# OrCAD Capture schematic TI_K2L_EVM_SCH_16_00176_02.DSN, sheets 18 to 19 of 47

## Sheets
18 PAGE31 : K2L_AMC SECTION: size C; title: AMC connector
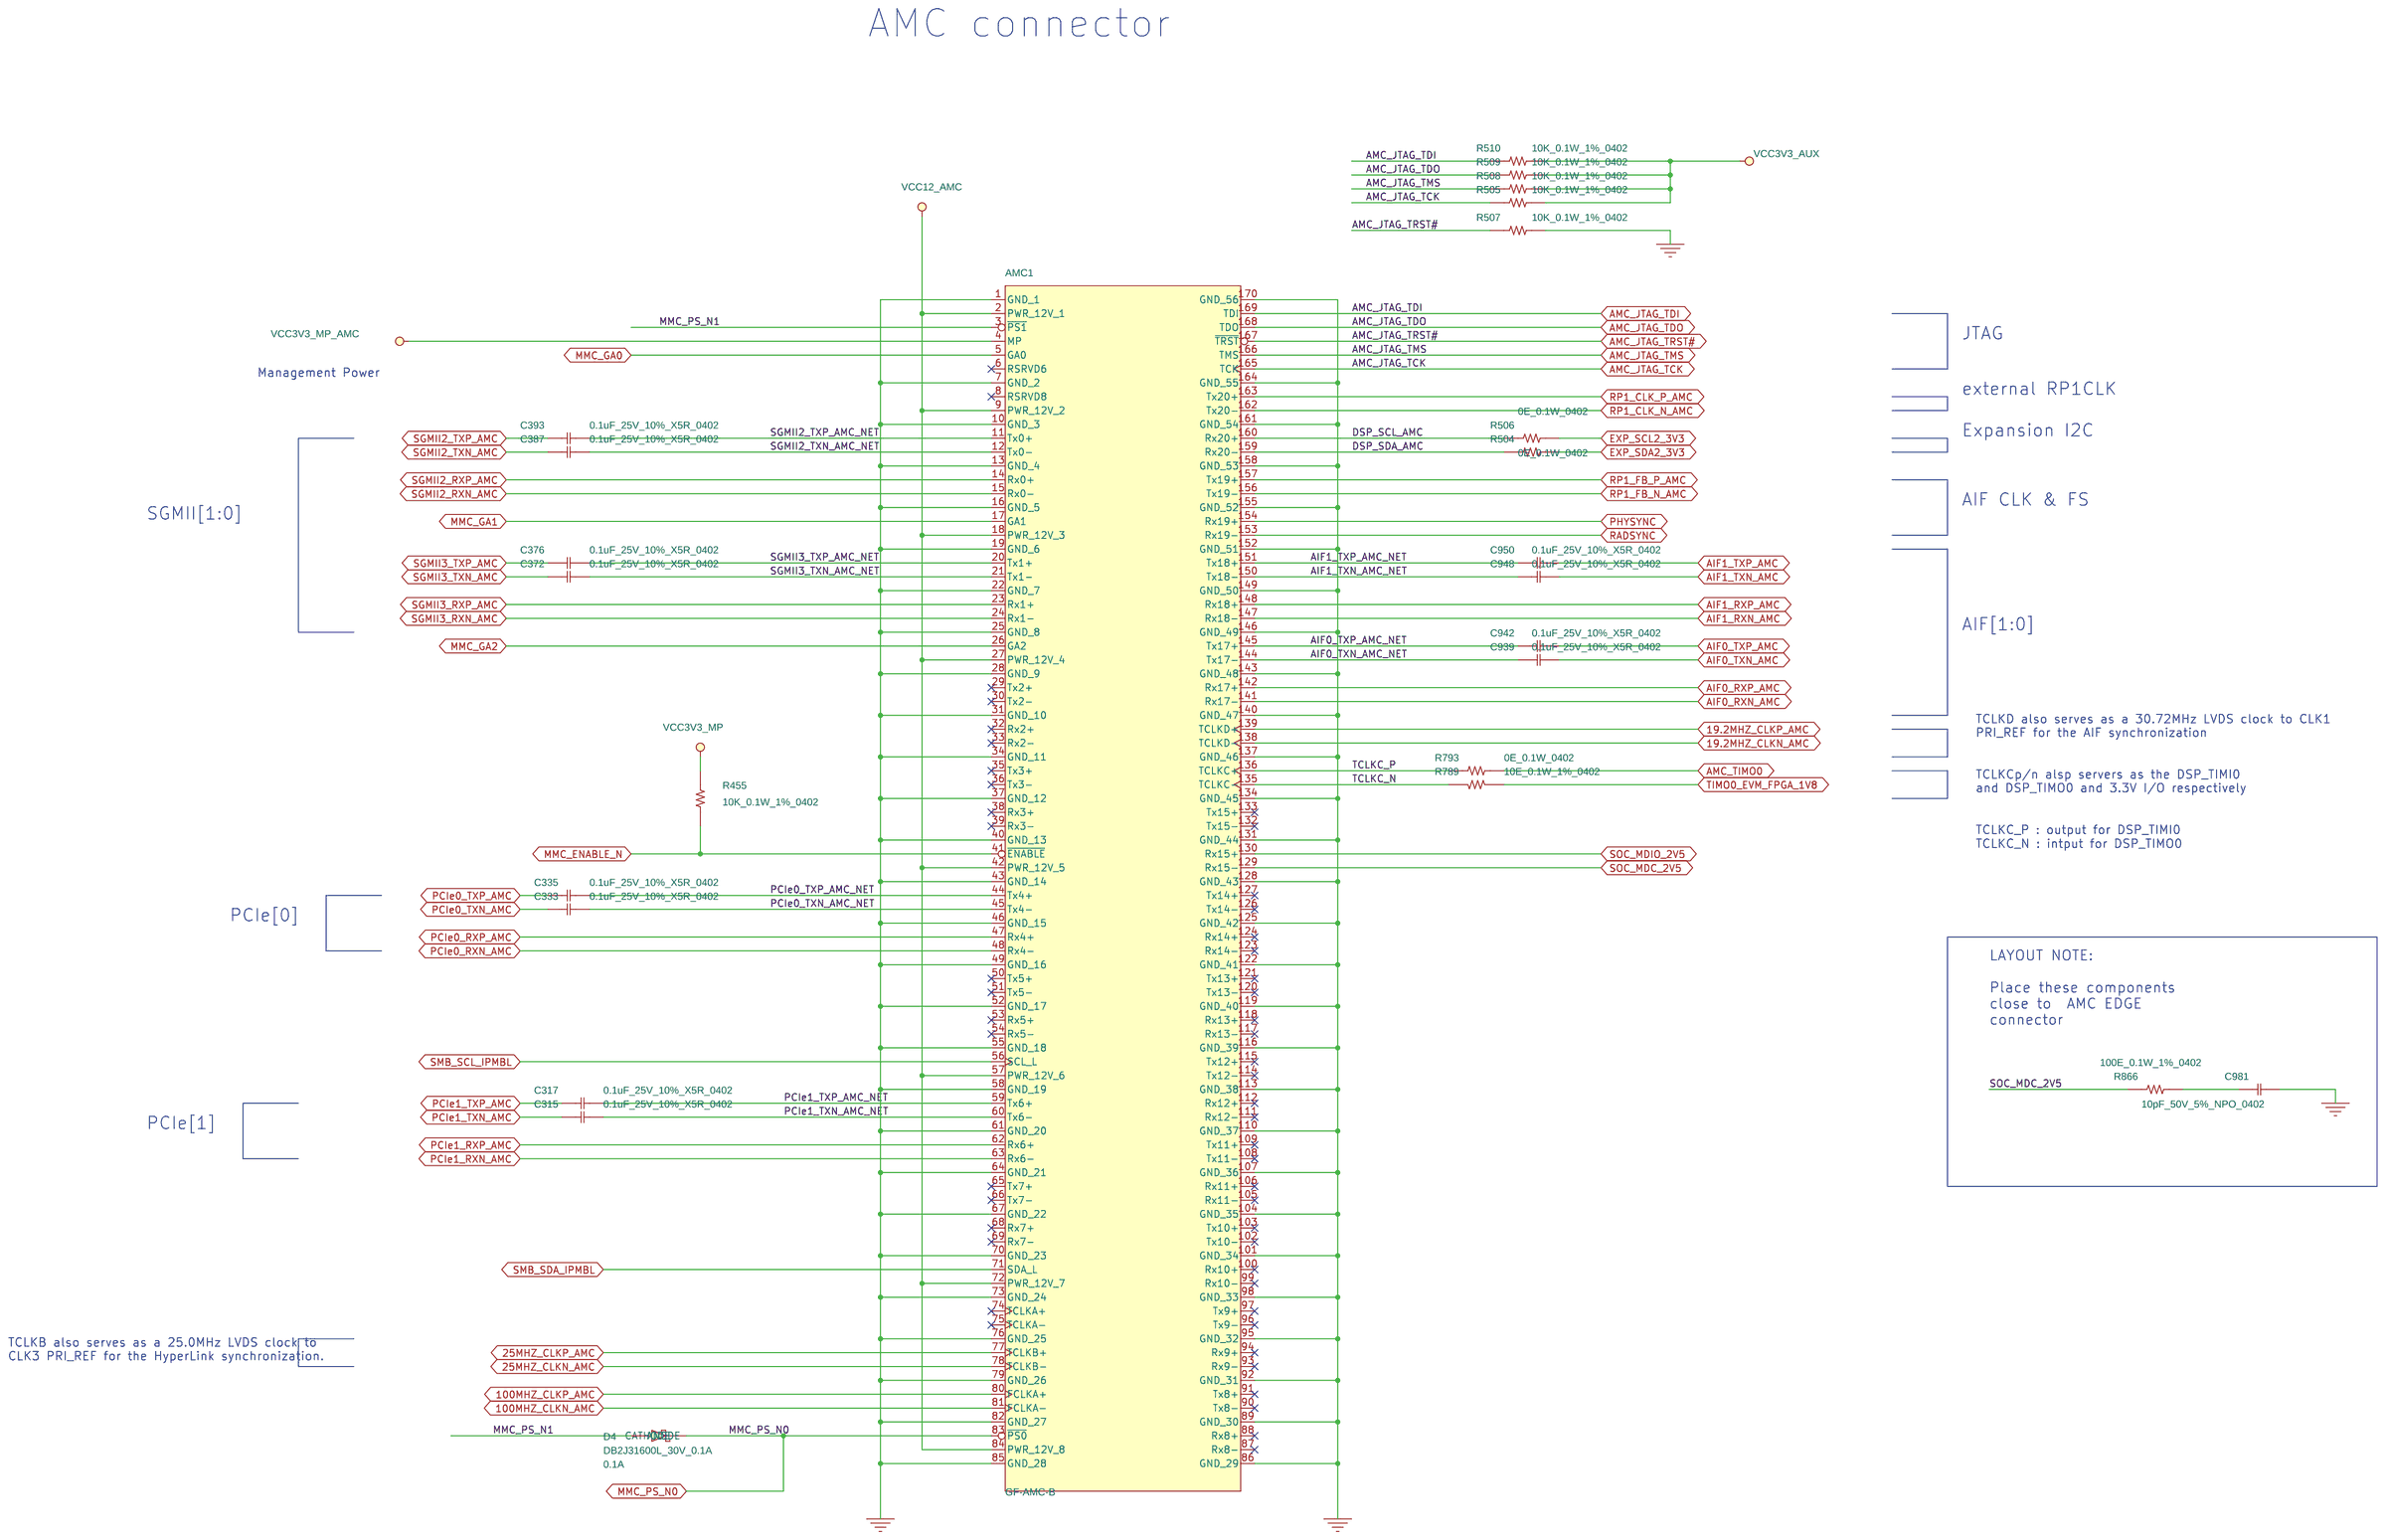
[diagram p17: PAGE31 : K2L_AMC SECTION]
19 PAGE21 : K2L_SOC-DDR3-3: size C; title: DDR3(2), 3.3vaux -> .75v DDR3 Vt, DDR3 SPD EEPROM
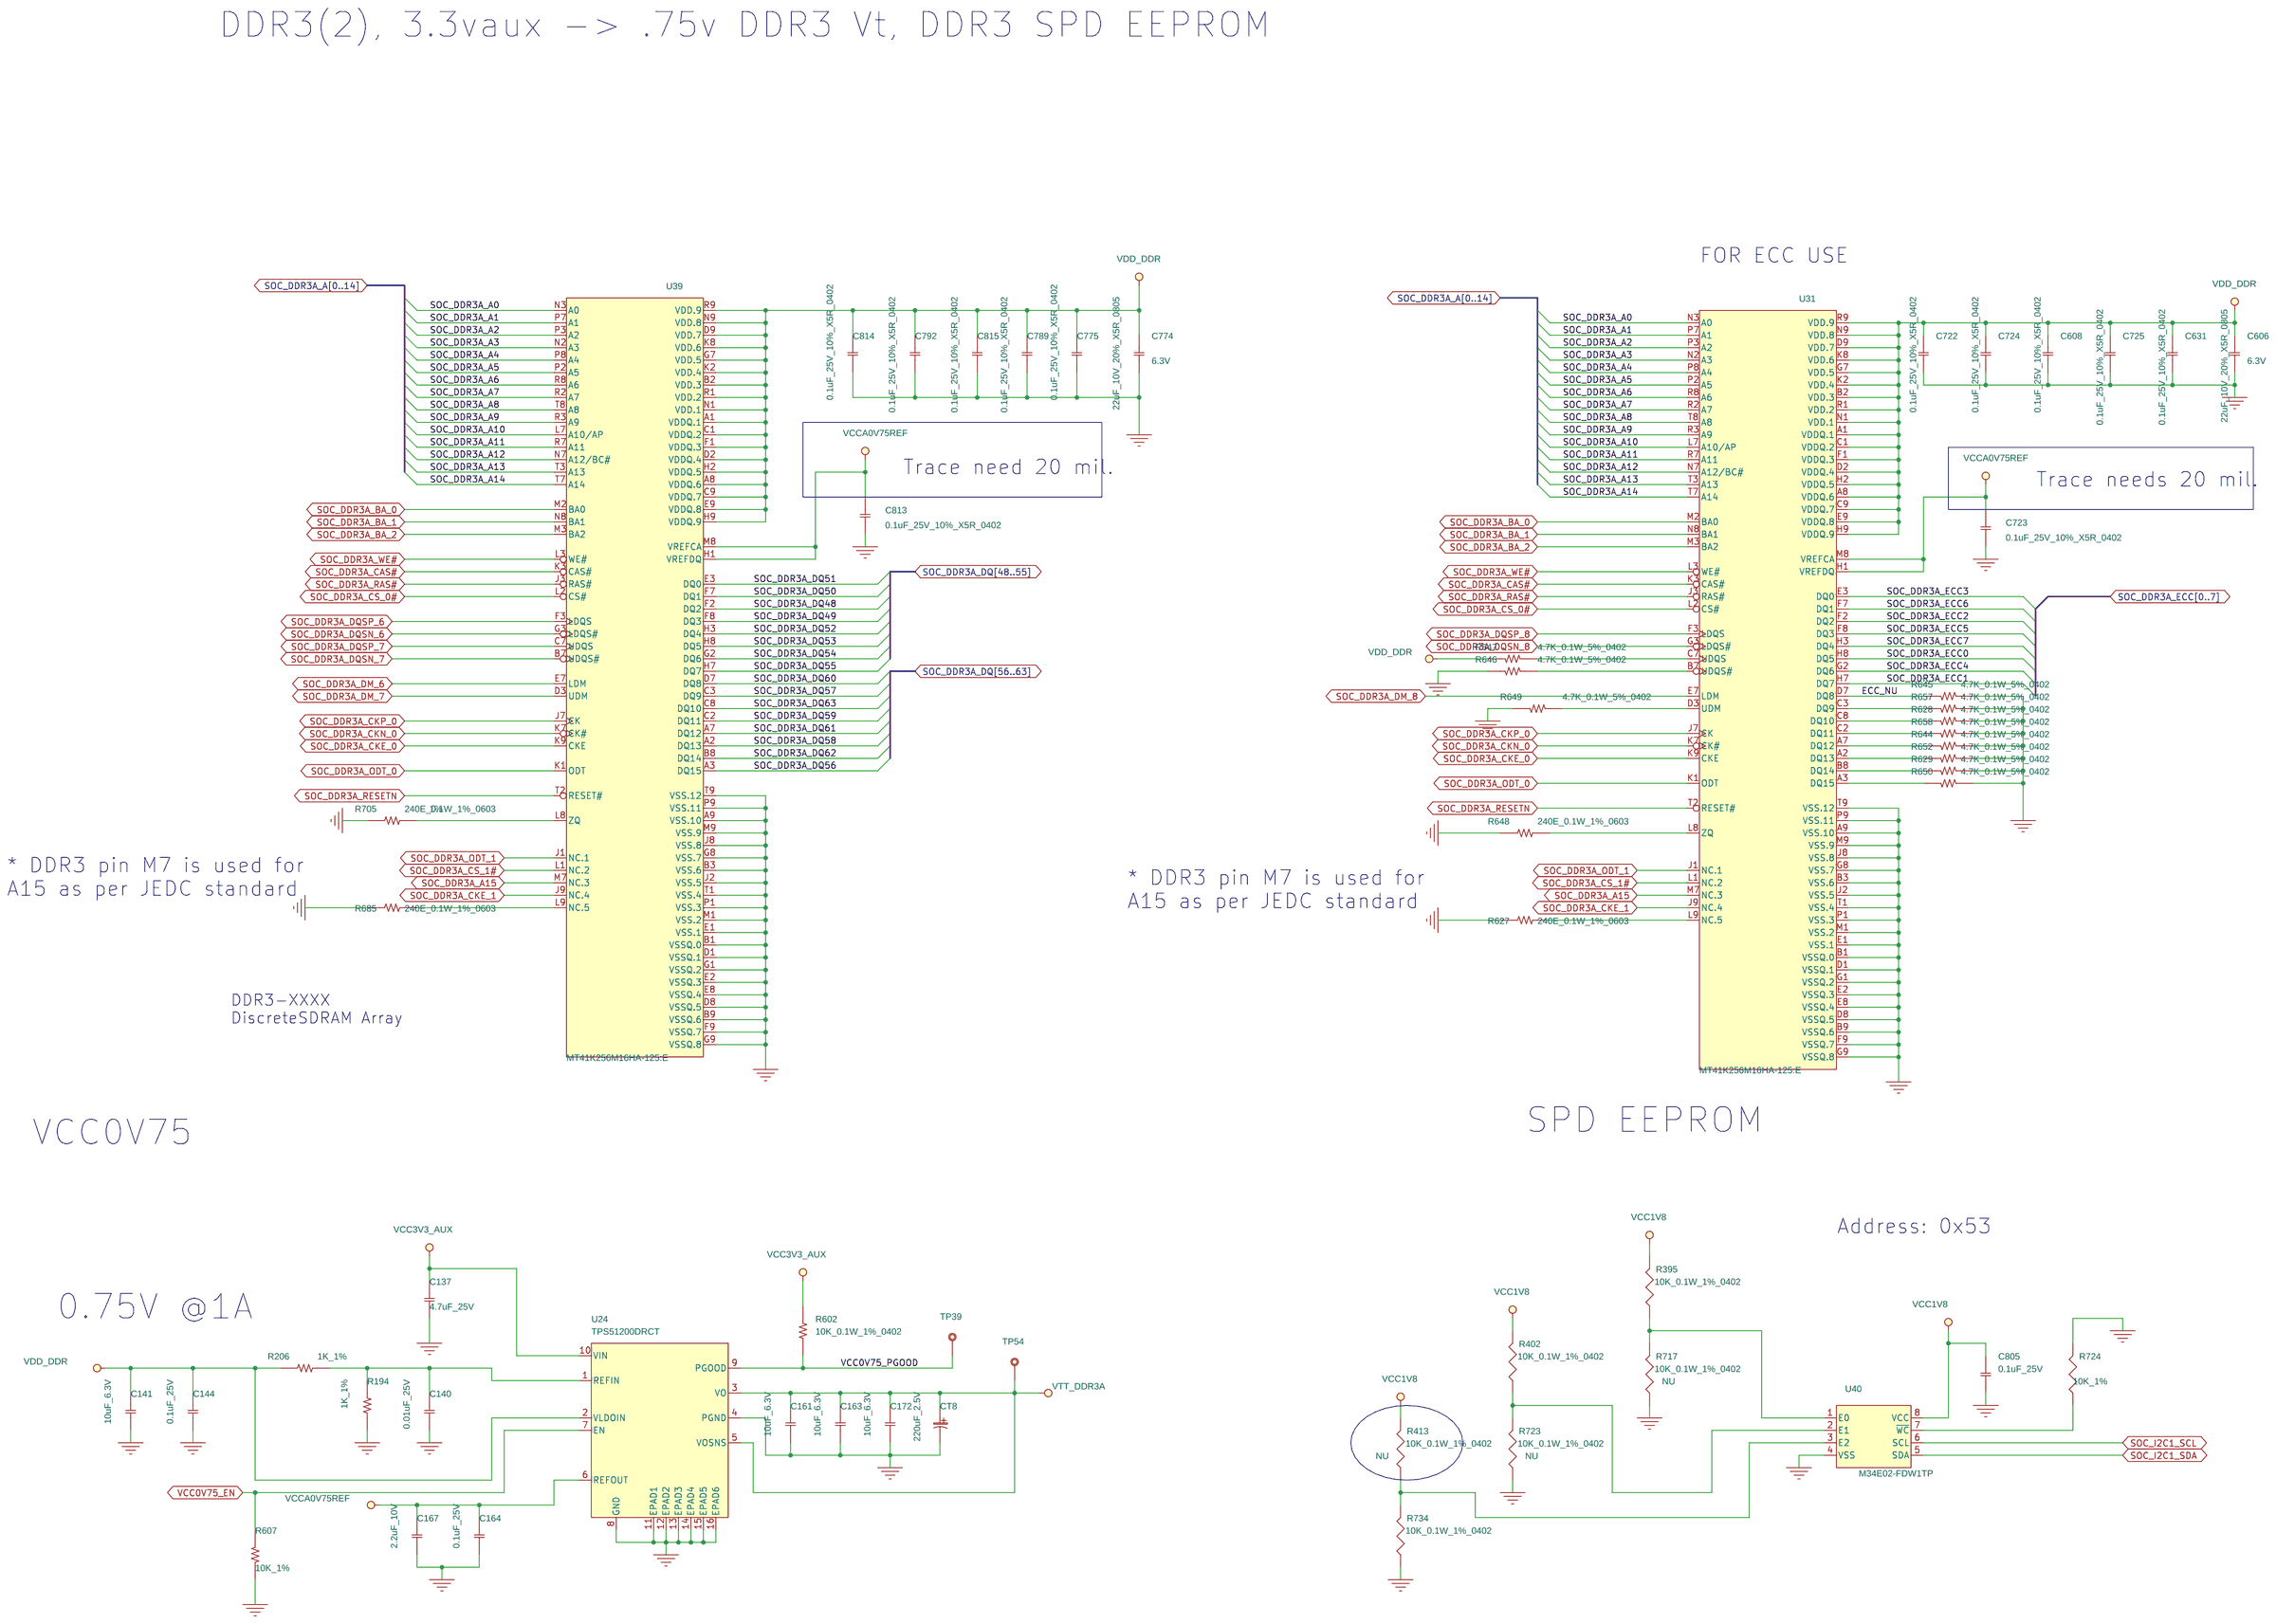
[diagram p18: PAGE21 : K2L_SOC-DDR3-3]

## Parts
sheet PAGE21 : K2L_SOC-DDR3-3
C137  4.7uF_25V  [C0603]
C140  0.01uF_25V  [C0402]
C141  10uF_6.3V  [C0603]
C144  0.1uF_25V  [C0402]
C161  10uF_6.3V  [C0603]
C163  10uF_6.3V  [C0603]
C164  0.1uF_25V  [C0402]
C167  2.2uF_10V  [C0402]
C172  10uF_6.3V  [C0603]
C606  22uF_10V_20%_X5R_0805  [C0805]
C608  0.1uF_25V_10%_X5R_0402  [C0402]
C631  0.1uF_25V_10%_X5R_0402  [C0402]
C722  0.1uF_25V_10%_X5R_0402  [C0402]
C723  0.1uF_25V_10%_X5R_0402  [C0402]
C724  0.1uF_25V_10%_X5R_0402  [C0402]
C725  0.1uF_25V_10%_X5R_0402  [C0402]
C774  22uF_10V_20%_X5R_0805  [C0805]
C775  0.1uF_25V_10%_X5R_0402  [C0402]
C789  0.1uF_25V_10%_X5R_0402  [C0402]
C792  0.1uF_25V_10%_X5R_0402  [C0402]
C805  0.1uF_25V  [C0402]
C813  0.1uF_25V_10%_X5R_0402  [C0402]
C814  0.1uF_25V_10%_X5R_0402  [C0402]
C815  0.1uF_25V_10%_X5R_0402  [C0402]
CT8  220uF_2.5V  [C_2P_114_138X118]
R194  1K_1%  [R0402]
R206  1K_1%  [R0402]
R395  10K_0.1W_1%_0402  [R0402]
R402  10K_0.1W_1%_0402  [R0402]
R413  10K_0.1W_1%_0402  [R0402]
R602  10K_0.1W_1%_0402  [R0402]
R607  10K_1%  [R0402]
R627  240E_0.1W_1%_0603  [R0603]
R628  4.7K_0.1W_5%_0402  [R0402]
R629  4.7K_0.1W_5%_0402  [R0402]
R644  4.7K_0.1W_5%_0402  [R0402]
R645  4.7K_0.1W_5%_0402  [R0402]
R646  4.7K_0.1W_5%_0402  [R0402]
R647  4.7K_0.1W_5%_0402  [R0402]
R648  240E_0.1W_1%_0603  [R0603]
R649  4.7K_0.1W_5%_0402  [R0402]
R650  4.7K_0.1W_5%_0402  [R0402]
R652  4.7K_0.1W_5%_0402  [R0402]
R657  4.7K_0.1W_5%_0402  [R0402]
R658  4.7K_0.1W_5%_0402  [R0402]
R685  240E_0.1W_1%_0603  [R0603]
R705  240E_0.1W_1%_0603  [R0603]
R717  10K_0.1W_1%_0402  [R0402]
R723  10K_0.1W_1%_0402  [R0402]
R724  10K_1%  [R0402]
R734  10K_0.1W_1%_0402  [R0402]
TP39  TP  [TP-S40]
TP54  TP  [TP-S40]
U24  TPS51200DRCT  [QFN10P_20_118x118_TP94x65V5]
U31  MT41K256M16HA-125:E  [FBGA80P_9X14_96_EINF]
U39  MT41K256M16HA-125:E  [FBGA80P_9X14_96_EINF]
U40  M34E02-FDW1TP  [TSSOP65P640_8]
sheet PAGE31 : K2L_AMC SECTION
AMC1  GF-AMC-B  [GF-AMC-B]
C315  0.1uF_25V_10%_X5R_0402  [C0402]
C317  0.1uF_25V_10%_X5R_0402  [C0402]
C333  0.1uF_25V_10%_X5R_0402  [C0402]
C335  0.1uF_25V_10%_X5R_0402  [C0402]
C372  0.1uF_25V_10%_X5R_0402  [C0402]
C376  0.1uF_25V_10%_X5R_0402  [C0402]
C387  0.1uF_25V_10%_X5R_0402  [C0402]
C393  0.1uF_25V_10%_X5R_0402  [C0402]
C939  0.1uF_25V_10%_X5R_0402  [C0402]
C942  0.1uF_25V_10%_X5R_0402  [C0402]
C948  0.1uF_25V_10%_X5R_0402  [C0402]
C950  0.1uF_25V_10%_X5R_0402  [C0402]
C981  10pF_50V_5%_NPO_0402  [C0402]
D4  DB2J31600L_30V_0.1A  [SODFL2512X80N]
R455  10K_0.1W_1%_0402  [R0402]
R504  0E_0.1W_0402  [R0402]
R505  10K_0.1W_1%_0402  [R0402]
R506  0E_0.1W_0402  [R0402]
R507  10K_0.1W_1%_0402  [R0402]
R508  10K_0.1W_1%_0402  [R0402]
R509  10K_0.1W_1%_0402  [R0402]
R510  10K_0.1W_1%_0402  [R0402]
R789  10E_0.1W_1%_0402  [R0402]
R793  0E_0.1W_0402  [R0402]
R866  100E_0.1W_1%_0402  [R0402]

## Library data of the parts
C137 = 11_C_0: CAP CER 4.7UF 25V 20% X5R 0603; Distributor_name: DIGIKEY; Distributor_part_number: 1276-1903-2-ND; EIC Part#: 03_00592_01; Manufacture: Samsung; Manufacture Part Number: CL10A475MA8NQNC; Manufacture(English): Samsung; Manufacture_Part_Number: CL10A475MA8NQNC; Manufacturer: Samsung; Manufacturer_Part_No: CL10A475MA8NQNC; Mfg: Samsung; Mfg Part#: CL10A475MA8NQNC; Mfr_name: Samsung; Mfr_part_number: CL10A475MA8NQNC; Oper. Temp. Range: -55C to 85C; Package: 0603; ProcessType: SMT; RoHS: Yes; Tolerance: 10%; Vendor: DIGIKEY; Vendor Part#: 1276-1903-2-ND; Vendor_Part_No: 1276-1903-2-ND; Voltage: 25V; eI Part#: 03_00592_01
C140 = 11_C_0: CAP CER 10000PF 25V 10% X7R 0402; Advansus_Part_Number: 11G232110312030; Characteristic: 16V; Distributor_name: DIGIKEY; Distributor_part_number: 445-1260-1-ND; EIC Part#: 03_00029_04; GROUP: CPU1; Manufacture: TDK Corporation; Manufacture Part Number: C1005X7R1E103K; Manufacture(English): TDK Corporation; Manufacture_Part_Number: C1005X7R1E103K; Manufacturer: TDK Corporation; Manufacturer_Part_No: C1005X7R1E103K; Mfg: TDK Corporation; Mfg Part#: 03_00029_04; Mfr_name: TDK Corporation; Mfr_part_number: C1005X7R1E103K; Package: 0402; Part_Number: 1121610790; Price @ 1: 0.10000; Price @ 10K: 0.00420; Price @ 1K: 0.00600; ProcessType: SMT; ROOM: CPU1; Tolerance: 10%; Vendor: DIGIKEY; Vendor_Part_No: 445-1260-1-ND; eI Part#: 03_00029_04
C141 C161 C163 C172 = 11_C_0: CAP CER 10UF 6.3V 20% X5R 0603; Avalue_Part_Number: E1121610610H; Characteristic: 6.3V; Distributor_name: DIGIKEY; Distributor_part_number: 587-3383-1-ND; EIC Part#: 03_00605_01; Manufacture: Taiyo Yuden; Manufacture Part Number: JMK107ABJ106MAHT; Manufacture(English): Taiyo Yuden; Manufacture_Part_Number: JMK107ABJ106MAHT; Manufacturer: Taiyo Yuden; Manufacturer_Part_No: JMK107ABJ106MAHT; Mfg: Taiyo Yuden; Mfg Part#: JMK107ABJ106MAHT; Mfr_name: Taiyo Yuden; Mfr_part_number: JMK107ABJ106MAHT; Package: 0603; Part_Number: 1100004184; Price @ 1: 0.32000; Price @ 10K: 0.06105; Price @ 1K: 0.07755; ProcessType: SMT; Tolerance: 20%; Vendor: DIGIKEY; Vendor Part#: 587-3383-1-ND; Vendor_Part_No: 587-3383-1-ND; eI Part#: 03_00605_01
C144 C315 C317 C333 C335 C372 C376 C387 C393 C939 C942 C948 C950 = 11_C_0: CAP CER 0.1UF 25V 10% X5R 0402; Avalue_Part_Number: E1123510400H; Distributor_name: DIGIKEY; Distributor_part_number: 445-4964-1-ND; EIC Part#: 03_00470_02; Manufacture: TDK Corporation; Manufacture Part Number: C1005X5R1E104K050BC; Manufacture(English): TDK Corporation; Manufacture_Part_Number: GRM155R71C104KA88D; Manufacturer: TDK Corporation; Manufacturer_Part_No: C1005X5R1E104K050BC; Mfg: Murata Electronics North America; Mfg Part#: 03_00470_02; Mfr_name: TDK Corporation; Mfr_part_number: C1005X5R1E104K050BC; Package: 0402; Price @ 1: 0.10000; Price @ 1K: 0.00420; ProcessType: SMT; Tolerance: 10%; Vendor: DIGIKEY; Vendor Part#: 445-4964-1-ND; Vendor_Part_No: 445-4964-1-ND; eI Part#: 03_00470_02
C164 C608 C631 C722-C725 C775 C789 C792 C805 C813-C815 = 11_C_0: CAP CER 0.1UF 25V 10% X5R 0402; Avalue_Part_Number: E1123510400H; Distributor_name: DIGIKEY; Distributor_part_number: 445-4964-1-ND; EIC Part#: 03_00470_02; MOUNTED: <MOUNTED>; Manufacture: TDK Corporation; Manufacture Part Number: C1005X5R1E104K050BC; Manufacture(English): TDK Corporation; Manufacture_Part_Number: GRM155R71C104KA88D; Manufacturer: TDK Corporation; Manufacturer_Part_No: C1005X5R1E104K050BC; Mfg: Murata Electronics North America; Mfg Part#: 03_00470_02; Mfr_name: TDK Corporation; Mfr_part_number: C1005X5R1E104K050BC; Package: 0402; Price @ 1: 0.10000; Price @ 1K: 0.00420; ProcessType: SMT; Tolerance: 10%; Vendor: DIGIKEY; Vendor Part#: 445-4964-1-ND; Vendor_Part_No: 445-4964-1-ND; eI Part#: 03_00470_02
C167 = 11_C_0: CAP CER 2.2UF 10V 10% X5R 0402; AVL_Part: AVL; Advansus_Part_Number: 11G233222516360; Characteristic: 10V; Distributor_name: DIGIKEY; Distributor_part_number: 445-7392-1-ND; EIC Part#: 03_00055_05; Manufacture: TDK Corporation; Manufacture Part Number: C1005X5R1A225K050BC; Manufacture(English): TDK Corporation; Manufacture_Part_Number: C1005X5R1A225K050BC; Manufacturer: TDK Corporation; Manufacturer_Part_No: C1005X5R1A225K050BC; Mfg: TDK Corporation; Mfg Part#: C1005X5R1A225K050BC; Mfr_name: TDK Corporation; Mfr_part_number: C1005X5R1A225K050BC; Package: 0402; Part_Number: 1100007233-01; Price @ 1: 0.13000; Price @ 10K: 0.01935; Price @ 1K: 0.02475; ProcessType: SMT; Tolerance: 10%; Vendor: DIGIKEY; Vendor_Part_No: 445-7392-1-ND; eI Part#: 03_00055_05
C606 C774 = 11_C_0: CAP CER 22UF 10V 20% X5R 0805; Characteristic: 6.3V; Distributor_name: DIGIKEY; Distributor_part_number: 587-1958-1-ND; EIC Part#: 03_00263_01; Manufacture: Taiyo Yuden; Manufacture Part Number: LMK212BJ226MG-T; Manufacture(English): Taiyo Yuden; Manufacture_Part_Number: LMK212BJ226MG-T; Manufacturer: Taiyo Yuden; Manufacturer_Part_No: LMK212BJ226MG-T; Mfg: Taiyo Yuden; Mfg Part#: 03_00263_01; Mfr_name: Taiyo Yuden; Mfr_part_number: LMK212BJ226MG-T; Package: 0805; Part_Number: 1100000254; Price @ 1: 0.53000; Price @ 10K: 0.12000; Price @ 1K: 0.16875; ProcessType: SMT; Tolerance: 20%; Vendor: DIGIKEY; Vendor Part#: 587-1958-1-ND; Vendor_Part_No: 587-1958-1-ND; eI Part#: 03_00263_01
CT8 = 11_C_POLAR_0: CAP TANT 220UF 2.5V 20% 1411; AVL_Part: AVL; Advansus_Part_Number: 11GA1100003905; Characteristic: 4V; Distributor_name: DIGIKEY; Distributor_part_number: P16210CT-ND; EIC Part#: TBD; Manufacture: Panasonic - ECG; Manufacture Part Number: 2R5TPE220MAZB; Manufacture(English): Panasonic - ECG; Manufacture_Part_Number: 2R5TPE220MAZB; Manufacturer: Panasonic - ECG; Manufacturer_Part_No: 2R5TPE220MAZB; Mfg: Panasonic Electronic Components; Mfg Part#: 2R5TPE220MAZB; Mfr_name: Panasonic - ECG; Mfr_part_number: 2R5TPE220MAZB; Package: PC-3.5*2.8*1.9mm; Part_Number: 1100003905; Price @ 1: 1.68000; Price @ 10K: 0.46942; Price @ 1K: 0.70413; ProcessType: SMT; Tolerance: 20%; Vendor: DIGIKEY; Vendor_Part_No: P16210CT-ND; eI Part#: TBD
R194 R206 = 10_R_0: RES 1.00K OHM 1/10W 1% 0402 SMD; Characteristic: 1%; Distributor_name: DIGIKEY; Distributor_part_number: P1.00KLCT-ND; EIC Part#: 02_00045_01; Manufacture: Panasonic - ECG; Manufacture Part Number: ERJ-2RKF1001X; Manufacture(English): Panasonic - ECG; Manufacture_Part_Number: ERJ-2RKF1001X; Manufacturer: Panasonic - ECG; Manufacturer_Part_No: ERJ-2RKF1001X; Mfg: Panasonic Electronic Components; Mfg Part#: 02_00045_01; Mfr_name: Panasonic - ECG; Mfr_part_number: ERJ-2RKF1001X; Package: 0402; Part_Number: 105A510014; Price @ 1: 0.10000; Price @ 10K: 0.00347; Price @ 1K: 0.00672; ProcessType: SMT; Tolerance: 1%; Vendor: DIGIKEY; Vendor_Part_No: P1.00KLCT-ND; eI Part#: 02_00045_01
R395 R402 R724 R734 = DISC_RESISTOR: RES 10K OHM 1/10W 1% 0402 SMD; Distributor_name: DIGIKEY; Distributor_part_number: P10.0KLCT-ND; EIC Part#: 02_00027_01; Manufacture: Panasonic - ECG; Manufacture Part Number: ERJ-2RKF1002X; Manufacture(English): Panasonic - ECG; Manufacture_Part_Number: ERJ-2RKF1002X; Manufacturer: Panasonic - ECG; Manufacturer_Part_No: ERJ-2RKF1002X; Mfg Part#: 02_00027_01; Mfr_name: Panasonic - ECG; Mfr_part_number: ERJ-2RKF1002X; Package: 0402; Price @ 1: 0.10000; Price @ 10K: 0.00347; Price @ 1K: 0.00672; RoHS Compliant?: RoHS Compliant; Vendor: DIGIKEY; Vendor_Part_No: P10.0KLCT-ND; eI Part#: 02_00027_01
R413 R717 R723 = DISC_RESISTOR: RES 10K OHM 1/10W 1% 0402 SMD; Distributor_name: DIGIKEY; Distributor_part_number: P10.0KLCT-ND; EIC Part#: 02_00027_01; Manufacture: Panasonic - ECG; Manufacture Part Number: ERJ-2RKF1002X; Manufacture(English): Panasonic - ECG; Manufacture_Part_Number: ERJ-2RKF1002X; Manufacturer: Panasonic - ECG; Manufacturer_Part_No: ERJ-2RKF1002X; Mfg Part#: 02_00027_01; Mfr_name: Panasonic - ECG; Mfr_part_number: ERJ-2RKF1002X; Mounting: NU; Mounting status: NU; Mounting_Status: NU; Package: 0402; Price @ 1: 0.10000; Price @ 10K: 0.00347; Price @ 1K: 0.00672; RoHS Compliant?: RoHS Compliant; Vendor: DIGIKEY; Vendor_Part_No: P10.0KLCT-ND; eI Part#: 02_00027_01
R505 R507-R510 R602 = 10_R_0: RES 10K OHM 1/10W 1% 0402 SMD; Characteristic: 1%; Distributor_name: DIGIKEY; Distributor_part_number: P10.0KLCT-ND; EIC Part#: 02_00027_01; Manufacture: Panasonic - ECG; Manufacture Part Number: ERJ-2RKF1002X; Manufacture(English): Panasonic - ECG; Manufacture_Part_Number: ERJ-2RKF1002X; Manufacturer: Panasonic - ECG; Manufacturer_Part_No: ERJ-2RKF1002X; Mfg: PANASONIC ELECTRONIC COMPONENTS (VA); Mfg Part#: 02_00027_01; Mfr_name: Panasonic - ECG; Mfr_part_number: ERJ-2RKF1002X; Package: 0402; Part_Number: 105A50103A; Price @ 1: 0.10000; Price @ 10K: 0.00347; Price @ 1K: 0.00672; ProcessType: SMT; Tolerance: 1%; Vendor: DIGIKEY; Vendor_Part_No: P10.0KLCT-ND; eI Part#: 02_00027_01
R607 = 10_R_0: RES 10K OHM 1/10W 1% 0402 SMD; Alt Mfg: Yageo; Alt Mfg Part#: RC0402FR-0710KL; Distributor_name: DIGIKEY; Distributor_part_number: P10.0KLCT-ND; EIC Part#: 02_00027_01; Manufacture: Panasonic - ECG; Manufacture Part Number: ERJ-2RKF1002X; Manufacture(English): Panasonic - ECG; Manufacture_Part_Number: ERJ-2RKF1002X; Manufacturer: Panasonic - ECG; Manufacturer_Part_No: ERJ-2RKF1002X; Mfg Part#: 02_00027_01; Mfr_name: Panasonic - ECG; Mfr_part_number: ERJ-2RKF1002X; Oper. Temp. Range: -55C to 125C; Package: 0402; Price @ 1: 0.10000; Price @ 10K: 0.00347; Price @ 1K: 0.00672; ProcessType: SMT; Remark: Alt part is 1/16W; RoHS: Yes; Tolerance: 1%; Vendor: DIGIKEY; Vendor Part#: P10.0KLCT-ND; Vendor_Part_No: P10.0KLCT-ND; eI Part#: 02_00027_01
R627 R685 = 10_R_0: RES 240 OHM 1/10W 1% 0603 SMD; Characteristic: 1%; Distributor_name: DIGIKEY; Distributor_part_number: P240HCT-ND; EIC Part#: 02_00734_01; Manufacture: Panasonic - ECG; Manufacture Part Number: ERJ-3EKF2400V; Manufacture(English): Panasonic - ECG; Manufacture_Part_Number: ERJ-3EKF2400V; Manufacturer: Panasonic - ECG; Manufacturer_Part_No: ERJ-3EKF2400V; Mfg: Panasonic Electronic Components; Mfg Part#: 02_00734_01; Mfr_name: Panasonic - ECG; Mfr_part_number: ERJ-3EKF2400V; Package: 0603; Part_Number: 105A524003; Price @ 1: 0.10000; Price @ 10K: 0.00247; Price @ 1K: 0.00416; ProcessType: SMT; Tolerance: 1%; Vendor: DIGIKEY; Vendor_Part_No: P240HCT-ND; eI Part#: 02_00027_01
R628 R629 R644-R647 R649 R650 R652 R657 R658 = 10_R_0: RES 4.7K OHM 1/10W 5% 0402 SMD; Advansus_Part_Number: 10G212472004030; Avalue_Part_Number: E1050704720H; Characteristic: 5%; Distributor_name: DIGIKEY; Distributor_part_number: P4.7KJCT-ND; EIC Part#: 02_00023_01; MOUNTED: <MOUNTED>; Manufacture: Panasonic - ECG; Manufacture Part Number: ERJ-2GEJ472X; Manufacture(English): Panasonic - ECG; Manufacture_Part_Number: ERJ-2GEJ472X; Manufacturer: Panasonic - ECG; Manufacturer_Part_No: ERJ-2GEJ472X; Mfg: Panasonic Electronic Components; Mfg Part#: 02_00266_01; Mfr_name: Panasonic - ECG; Mfr_part_number: ERJ-2GEJ472X; Package: 0402; Part_Number: 105A747014; Price @ 1: 0.10000; Price @ 10K: 0.00347; Price @ 1K: 0.00672; ProcessType: SMT; Tolerance: 5%; Vendor: DIGIKEY; Vendor_Part_No: P4.7KJCT-ND; eI Part#: 02_00023_01
R648 R705 = 10_R_0: RES 240 OHM 1/10W 1% 0603 SMD; Characteristic: 1%; Distributor_name: DIGIKEY; Distributor_part_number: P240HCT-ND; EIC Part#: 02_00734_01; Manufacture: Panasonic - ECG; Manufacture Part Number: ERJ-3EKF2400V; Manufacture(English): Panasonic - ECG; Manufacture_Part_Number: ERJ-3EKF2400V; Manufacturer: Panasonic - ECG; Manufacturer_Part_No: ERJ-3EKF2400V; Mfg: Panasonic Electronic Components; Mfg Part#: 02_00734_01; Mfr_name: Panasonic - ECG; Mfr_part_number: ERJ-3EKF2400V; Package: 0603; Part_Number: 105A524003; Price @ 1: 0.10000; Price @ 10K: 0.00247; Price @ 1K: 0.00416; ProcessType: SMT; Tolerance: 1%; Vendor: DIGIKEY; Vendor_Part_No: P240HCT-ND; eI Part#: 02_00195_04
TP39 TP54 = 00_TP28_0: TEST PAD TP; Advansus_Part_Number: 0030000003; Avalue_Part_Number: 0030000003; Distributor_name: NA; Distributor_part_number: NA; EIC Part#: NA; Manufacture: NA; Manufacture Part Number: NA; Manufacture(English): NA; Manufacture_Part_Number: NA; Manufacturer: NA; Manufacturer_Part_No: NA; Mfg: NA; Mfg Part#: NA; Mfr_name: NA; Mfr_part_number: NA; Part_Number: 0030000003; Price @ 1: NA; Price @ 10K: NA; Price @ 1K: NA; ProcessType: SMT; Vendor: NA; Vendor_Part_No: NA; eI Part#: NA
U24 = TPS51200DRCT_1: IC SINK/SOURCE DDR REG 10-SON; Distributor_name: DIGIKEY; Distributor_part_number: 296-23830-1-ND; EIC Part#: 01_00725_02; Manufacture: TI; Manufacture(English): TI; Manufacturer: TI; Mfg: TI; Mfg Part#: 01_00725_02; Mfr_name: TI; Oper. Temp. Range: -40°C ~ 85°C; Package: SON10; Price @ 1: 2.58000; Price @ 1K: 1.07324; ProcessType: SMT; RoHS: Yes; Vendor: DIGIKEY; Vendor Part#: 296-23830-1-ND; Vendor_Part_No: 296-23830-1-ND; eI Part#: 01_00844_01
U31 U39 = MT41K256M16HA_0: IC DDR3 SDRAM 4GBIT 96FBGA; Distributor_name: DIGIKEY; Distributor_part_number: MT41K256M16HA-125:E-ND; EIC Part#: 01_01147_01; Manufacture: Micron; Manufacture(English): Micron; Manufacturer: Micron; Mfg Part#: 01_01147_01; Mfr_name: Micron; Price @ 1K: 8.65215; Vendor: DIGIKEY; Vendor part#: MT41K256M16HA125:E; Vendor_Part_No: MT41K256M16HA-125:E-ND; eI Part#: 01_01149_01; itemp Part#: MT41K256M16HA125:E
U40 = M34E02-FDW1TP: IC EEPROM 2KBIT 400KHZ 8TSSOP; Distributor_name: DIGIKEY; Distributor_part_number: 497-8654-1-ND; EIC Part#: 01_01146_01; Manufacture: STMicroelectronics; Manufacture(English): STMicroelectronics; Manufacturer: STMicroelectronics; Mfg: STMicroelectronics; Mfg Part#: 01_01146_01; Mfr_name: STMicroelectronics; Price @ 1: 0.69000; Price @ 10K: 0.22010; Price @ 1K: 0.22010; Vendor: DIGIKEY; Vendor_Part_No: 497-8654-1-ND; eI Part#: 08_00006_01
AMC1 = 00_GF-AMC-B_0: GOLD-FINGER  AMC-B  170P; Distributor_name: NA; Distributor_part_number: NA; EIC Part#: NA; Manufacture: NA; Manufacture Part Number: NA; Manufacture(English): NA; Manufacture_Part_Number: NA; Manufacturer: NA; Manufacturer_Part_No: NA; Mfg: NA; Mfg Part#: NA; MfrNum: 3; Mfr_name: NA; Mfr_part_number: NA; Part Number: 2; Price @ 1: NA; Price @ 10K: NA; Price @ 1K: NA; Vendor: NA; Vendor_Part_No: NA; eI Part#: NA
C981 = 11_C_0: CAP CER 10PF 50V 5% NPO 0402; Advansus_Part_Number: 11G232010004030; Characteristic: 50V; Distributor_name: DIGIKEY; Distributor_part_number: 490-5921-6-ND; EIC Part#: 03_00366_03; Manufacture: Murata; Manufacture Part Number: GRM1555C1H100JA01D; Manufacture(English): Murata; Manufacture_Part_Number: CC0402JRNPO9BN100; Manufacturer: Murata; Manufacturer_Part_No: GRM1555C1H100JA01D; Mfg: Yageo; Mfg Part#: 03_00366_03; Mfr_name: Murata; Mfr_part_number: GRM1555C1H100JA01D; Package: 0402; Part_Number: 1124410091; Price @ 1: 0.10000; Price @ 10K: 0.00227; Price @ 1K: 0.00324; ProcessType: SMT; Tolerance: 5%; Vendor: DIGIKEY; Vendor_Part_No: 490-5921-6-ND; eI Part#: 03_00366_03
D4 = 130_SCHOTTKY_0805_1: DIODE SCHOTTKY 30V 0.1A SMINI2; AVL_Part: Non-AVL; Characteristic: 0.1A; Distributor_name: DIGIKEY; Distributor_part_number: DB2J31600LCT-ND; EIC Part#: TBD; Manufacture: Panasonic - ECG; Manufacture Part Number: DB2J31600L; Manufacture(English): Panasonic - ECG; Manufacture_Part_Number: DB2J31600L; Manufacturer: Panasonic - ECG; Manufacturer_Part_No: DB2J31600L; Mfg: Panasonic Electronic Components - Semiconductor Products; Mfg Part#: TBD; Mfr_name: Panasonic - ECG; Mfr_part_number: DB2J31600L; Package: 0805; Part_Number: 1300001849; Price @ 1: 0.21000; Price @ 10K: 0.03450; Price @ 1K: 0.03945; ProcessType: SMT; Vendor: DIGIKEY; Vendor_Part_No: DB2J31600LCT-ND; eI Part#: TBD
R455 = 10_R_0: RES 10K OHM 1/10W 1% 0402 SMD; Characteristic: 1%; Distributor_name: DIGIKEY; Distributor_part_number: P10.0KLCT-ND; EIC Part#: 02_00027_01; MOUNTED: <MOUNTED>; Manufacture: Panasonic - ECG; Manufacture Part Number: ERJ-2RKF1002X; Manufacture(English): Panasonic - ECG; Manufacture_Part_Number: ERJ-2RKF1002X; Manufacturer: Panasonic - ECG; Manufacturer_Part_No: ERJ-2RKF1002X; Mfg: PANASONIC ELECTRONIC COMPONENTS (VA); Mfg Part#: 02_00027_01; Mfr_name: Panasonic - ECG; Mfr_part_number: ERJ-2RKF1002X; Package: 0402; Part_Number: 105A50103A; Price @ 1: 0.10000; Price @ 10K: 0.00347; Price @ 1K: 0.00672; ProcessType: SMT; Tolerance: 1%; Vendor: DIGIKEY; Vendor_Part_No: P10.0KLCT-ND; eI Part#: 02_00027_01
R504 R506 R793 = 10_R_0: RES 0.0 OHM 1/10W JUMP 0402 SMD; Characteristic: 5%; Distributor_name: DIGIKEY; Distributor_part_number: P0.0JCT-ND; EIC Part#: 02_00019_01; MOUNTED: <MOUNTED>; Manufacture: Panasonic - ECG; Manufacture Part Number: ERJ-2GE0R00X; Manufacture(English): Panasonic - ECG; Manufacture_Part_Number: ERJ-2GE0R00X; Manufacturer: Panasonic - ECG; Manufacturer_Part_No: ERJ-2GE0R00X; Mfg: Panasonic Electronic Components; Mfg Part#: 02_00019_01; Mfr_name: Panasonic - ECG; Mfr_part_number: ERJ-2GE0R00X; Package: 0402; Part_Number: 105A700004; Price @ 1: 0.05000; Price @ 10K: 0.00248; Price @ 1K: 0.00480; ProcessType: SMT; Tolerance: 5%; Vendor: DIGIKEY; Vendor_Part_No: P0.0JCT-ND; eI Part#: 02_00019_01
R789 = 10_R_0: RES 10.0 OHM 1/10W 1% 0402 SMD; Characteristic: 5%; Distributor_name: DIGIKEY; Distributor_part_number: P10.0LCT-ND; EIC Part#: 02_00348_01; Manufacture: Panasonic - ECG; Manufacture Part Number: ERJ-2RKF10R0X; Manufacture(English): Panasonic - ECG; Manufacture_Part_Number: ERJ-2RKF10R0X; Manufacturer: Panasonic - ECG; Manufacturer_Part_No: ERJ-2RKF10R0X; Mfg: Panasonic Electronic Components; Mfg Part#: ERJ-2RKF10R0X; Mfr_name: Panasonic - ECG; Mfr_part_number: ERJ-2RKF10R0X; Package: 0402; Part_Number: 105A701004; Price @ 1: 0.10000; Price @ 10K: 0.00248; Price @ 1K: 0.00480; ProcessType: SMT; Tolerance: 5%; Vendor: DIGIKEY; Vendor_Part_No: P10.0LCT-ND; eI Part#: 02_00348_01
R866 = 10_R_0: RES 100 OHM 1/10W 1% 0402 SMD; Distributor_name: DIGIKEY; Distributor_part_number: P100LCT-ND; EIC Part#: 02_00043_02; Manufacture: Panasonic - ECG; Manufacture Part Number: ERJ-2RKF1000X; Manufacture(English): Panasonic - ECG; Manufacture_Part_Number: ERJ-2RKF1000X; Manufacturer: Panasonic - ECG; Manufacturer_Part_No: ERJ-2RKF1000X; Mfg Part#: 02_00043_02; Mfr_name: Panasonic - ECG; Mfr_part_number: ERJ-2RKF1000X; Oper. Temp. Range: -55C to 125C; Package: 0402; ProcessType: SMT; RoHS: Yes; Tolerance: 1%; Vendor: DIGIKEY; Vendor Part#: P100LCT-ND; Vendor_Part_No: P100LCT-ND; eI Part#: 02_00019_01

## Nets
GND: AMC1.1(GND) AMC1.7(GND_2) AMC1.10(GND_3) AMC1.13(GND_4) AMC1.16(GND_5) AMC1.19(GND_6) AMC1.22(GND_7) AMC1.25(GND_8) AMC1.28(GND_9) AMC1.31(GND_10) AMC1.34(GND_11) AMC1.37(GND_12) AMC1.40(GND_13) AMC1.43(GND_14) AMC1.46(GND_15) AMC1.49(GND_16) AMC1.52(GND_17) AMC1.55(GND_18) AMC1.58(GND_19) AMC1.61(GND_20) AMC1.64(GND_21) AMC1.67(GND_22) AMC1.70(GND_23) AMC1.73(GND_24) AMC1.76(GND_25) AMC1.79(GND_26) AMC1.82(GND_27) AMC1.85(GND_28) AMC1.86(GND_29) AMC1.89(GND_30) AMC1.92(GND_31) AMC1.95(GND_32) AMC1.98(GND_33) AMC1.101(GND_34) AMC1.104(GND_35) AMC1.107(GND_36) AMC1.110(GND_37) AMC1.113(GND_38) AMC1.116(GND_39) AMC1.119(GND_40) AMC1.122(GND_41) AMC1.125(GND_42) AMC1.128(GND_43) AMC1.131(GND_44) AMC1.134(GND_45) AMC1.137(GND_46) AMC1.140(GND_47) AMC1.143(GND_48) AMC1.146(GND_49) AMC1.149(GND_50) AMC1.152(GND_51) AMC1.155(GND_52) AMC1.158(GND_53) AMC1.161(GND_54) AMC1.164(GND_55) AMC1.170(GND_56) C137.2 C140.2 C141.1 C144.1 C161.1 C163.1 C164.2 C167.1 C172.1 C606.2 C608.2 C631.2 C722.2 C723.2 C724.2 C725.2 C774.2 C775.2 C789.2 C792.2 C805.2 C813.2 C814.2 C815.2 C981.2 CT8.2 R194.2 R507.1 R607.1 R627.1 R628.1 R629.1 R644.1 R645.1 R646.2 R648.1 R649.2 R650.1 R652.1 R657.1 R658.1 R685.1 R705.1 R717.1 R723.1 R724.2 R734.1 U24.4(PGND) U24.8(GND) U24.11(EPAD1) U24.12(EPAD2) U24.13(EPAD3) U24.14(EPAD4) U24.15(EPAD5) U24.16(EPAD6) U31.A9(VSS.10) U31.B1(VSSQ.0) U31.B3(VSS.6) U31.B9(VSSQ.6) U31.D1(VSSQ.1) U31.D8(VSSQ.5) U31.E1(VSS.1) U31.E2(VSSQ.3) U31.E8(VSSQ.4) U31.F9(VSSQ.7) U31.G1(VSSQ.2) U31.G8(VSS.7) U31.G9(VSSQ.8) U31.J2(VSS.5) U31.J8(VSS.8) U31.M1(VSS.2) U31.M9(VSS.9) U31.P1(VSS.3) U31.P9(VSS.11) U31.T1(VSS.4) U31.T9(VSS.12) U39.A9(VSS.10) U39.B1(VSSQ.0) U39.B3(VSS.6) U39.B9(VSSQ.6) U39.D1(VSSQ.1) U39.D8(VSSQ.5) U39.E1(VSS.1) U39.E2(VSSQ.3) U39.E8(VSSQ.4) U39.F9(VSSQ.7) U39.G1(VSSQ.2) U39.G8(VSS.7) U39.G9(VSSQ.8) U39.J2(VSS.5) U39.J8(VSS.8) U39.M1(VSS.2) U39.M9(VSS.9) U39.P1(VSS.3) U39.P9(VSS.11) U39.T1(VSS.4) U39.T9(VSS.12) U40.4(VSS) ; also on sheet 1 2 3 4 5 6 8 10 11 12 13 14 15 16 17 20 21 22 24 25 26 27 28 29 33 34 35 36 37 40 41 42 43 45 46 47
VCC0V75_EN: R607.2 U24.7(EN) ; also on sheet 37
VCC0V75_PGOOD: R602.1 TP39.1 U24.9(PGOOD)
VCC1V8: C805.1 R395.2 R402.2 R413.2 U40.8(VCC) ; also on sheet 2 6 8 11 21 22 25 26 27 29 33 34 36 37 41
VCC3V3_AUX: C137.1 R505.1 R508.1 R509.1 R510.1 R602.2 U24.10(VIN) ; also on sheet 2 4 6 8 11 12 13 16 22 25 26 27 28 29 33 35 37 40 45 47
VCC3V3_MP: R455.2 ; also on sheet 4 5 22 37 41
VCC3V3_MP_AMC: AMC1.4(MP) ; also on sheet 5
VCC12_AMC: AMC1.2(PWR_12V_1) AMC1.9(PWR_12V_2) AMC1.18(PWR_12V_3) AMC1.27(PWR_12V_4) AMC1.42(PWR_12V_5) AMC1.57(PWR_12V_6) AMC1.72(PWR_12V_7) AMC1.84(PWR_12V_8) ; also on sheet 25
VCCA0V75REF: C164.1 C167.2 C723.1 C813.1 U24.6(REFOUT) U31.H1(VREFDQ) U31.M8(VREFCA) U39.H1(VREFDQ) U39.M8(VREFCA) ; also on sheet 1 20
VDD_DDR: C141.2 C144.2 C606.1 C608.1 C631.1 C722.1 C724.1 C725.1 C774.1 C775.1 C789.1 C792.1 C814.1 C815.1 R206.1 R647.2 U24.2(VLDOIN) U31.A1(VDDQ.1) U31.A8(VDDQ.6) U31.B2(VDD.3) U31.C1(VDDQ.2) U31.C9(VDDQ.7) U31.D2(VDDQ.4) U31.D9(VDD.7) U31.E9(VDDQ.8) U31.F1(VDDQ.3) U31.G7(VDD.5) U31.H2(VDDQ.5) U31.H9(VDDQ.9) U31.K2(VDD.4) U31.K8(VDD.6) U31.N1(VDD.1) U31.N9(VDD.8) U31.R1(VDD.2) U31.R9(VDD.9) U39.A1(VDDQ.1) U39.A8(VDDQ.6) U39.B2(VDD.3) U39.C1(VDDQ.2) U39.C9(VDDQ.7) U39.D2(VDDQ.4) U39.D9(VDD.7) U39.E9(VDDQ.8) U39.F1(VDDQ.3) U39.G7(VDD.5) U39.H2(VDDQ.5) U39.H9(VDDQ.9) U39.K2(VDD.4) U39.K8(VDD.6) U39.N1(VDD.1) U39.N9(VDD.8) U39.R1(VDD.2) U39.R9(VDD.9) ; also on sheet 1 20 33 35 37
19.2MHZ_CLKN_AMC: AMC1.138(TCLKD-) ; also on sheet 16
19.2MHZ_CLKP_AMC: AMC1.139(TCLKD+) ; also on sheet 16
25MHZ_CLKN_AMC: AMC1.78(TCLKB-) ; also on sheet 16
25MHZ_CLKP_AMC: AMC1.77(TCLKB+) ; also on sheet 16
100MHZ_CLKN_AMC: AMC1.81(FCLKA-) ; also on sheet 4
100MHZ_CLKP_AMC: AMC1.80(FCLKA+) ; also on sheet 4
AIF0_RXN_AMC: AMC1.141(Rx17-) ; also on sheet 45
AIF0_RXP_AMC: AMC1.142(Rx17+) ; also on sheet 45
AIF0_TXN_AMC: C939.2 ; also on sheet 45
AIF0_TXN_AMC_NET: AMC1.144(Tx17-) C939.1
AIF0_TXP_AMC: C942.2 ; also on sheet 45
AIF0_TXP_AMC_NET: AMC1.145(Tx17+) C942.1
AIF1_RXN_AMC: AMC1.147(Rx18-) ; also on sheet 45
AIF1_RXP_AMC: AMC1.148(Rx18+) ; also on sheet 45
AIF1_TXN_AMC: C948.2 ; also on sheet 45
AIF1_TXN_AMC_NET: AMC1.150(Tx18-) C948.1
AIF1_TXP_AMC: C950.2 ; also on sheet 45
AIF1_TXP_AMC_NET: AMC1.151(Tx18+) C950.1
AMC_JTAG_TCK: AMC1.165(TCK) R505.2 ; also on sheet 6
AMC_JTAG_TDI: AMC1.169(TDI) R510.2 ; also on sheet 6
AMC_JTAG_TDO: AMC1.168(TDO) R509.2 ; also on sheet 6
AMC_JTAG_TMS: AMC1.166(TMS) R508.2 ; also on sheet 6
AMC_JTAG_TRST#: AMC1.167(~{TRST}) R507.2 ; also on sheet 6
AMC_TIMO0: R793.2 ; also on sheet 28
DSP_SCL_AMC: AMC1.160(Rx20+) R506.1
DSP_SDA_AMC: AMC1.159(Rx20-) R504.1
ECC_NU: R645.2 U31.D7(DQ8)
EXP_SCL2_3V3: R506.2 ; also on sheet 26
EXP_SDA2_3V3: R504.2 ; also on sheet 26
MMC_ENABLE_N: AMC1.41(~{ENABLE}) R455.1 ; also on sheet 5
MMC_GA0: AMC1.5(GA0) ; also on sheet 5
MMC_GA1: AMC1.17(GA1) ; also on sheet 5
MMC_GA2: AMC1.26(GA2) ; also on sheet 5
MMC_PS_N0: AMC1.83(~{PS0}) D4.1(CATHODE) ; also on sheet 5
MMC_PS_N1: AMC1.3(~{PS1}) D4.2(ANODE)
PCIe0_RXN_AMC: AMC1.48(Rx4-) ; also on sheet 40
PCIe0_RXP_AMC: AMC1.47(Rx4+) ; also on sheet 40
PCIe0_TXN_AMC: C333.1 ; also on sheet 40
PCIe0_TXN_AMC_NET: AMC1.45(Tx4-) C333.2
PCIe0_TXP_AMC: C335.1 ; also on sheet 40
PCIe0_TXP_AMC_NET: AMC1.44(Tx4+) C335.2
PCIe1_RXN_AMC: AMC1.63(Rx6-) ; also on sheet 40
PCIe1_RXP_AMC: AMC1.62(Rx6+) ; also on sheet 40
PCIe1_TXN_AMC: C315.1 ; also on sheet 40
PCIe1_TXN_AMC_NET: AMC1.60(Tx6-) C315.2
PCIe1_TXP_AMC: C317.1 ; also on sheet 40
PCIe1_TXP_AMC_NET: AMC1.59(Tx6+) C317.2
PHYSYNC: AMC1.154(Rx19+) ; also on sheet 26 29
RADSYNC: AMC1.153(Rx19-) ; also on sheet 26 29
RP1_CLK_N_AMC: AMC1.162(Tx20-) ; also on sheet 16
RP1_CLK_P_AMC: AMC1.163(Tx20+) ; also on sheet 16
RP1_FB_N_AMC: AMC1.156(Tx19-) ; also on sheet 16
RP1_FB_P_AMC: AMC1.157(Tx19+) ; also on sheet 16
SGMII2_RXN_AMC: AMC1.15(Rx0-) ; also on sheet 40
SGMII2_RXP_AMC: AMC1.14(Rx0+) ; also on sheet 40
SGMII2_TXN_AMC: C387.1 ; also on sheet 40
SGMII2_TXN_AMC_NET: AMC1.12(Tx0-) C387.2
SGMII2_TXP_AMC: C393.1 ; also on sheet 40
SGMII2_TXP_AMC_NET: AMC1.11(Tx0+) C393.2
SGMII3_RXN_AMC: AMC1.24(Rx1-) ; also on sheet 40
SGMII3_RXP_AMC: AMC1.23(Rx1+) ; also on sheet 40
SGMII3_TXN_AMC: C372.1 ; also on sheet 40
SGMII3_TXN_AMC_NET: AMC1.21(Tx1-) C372.2
SGMII3_TXP_AMC: C376.1 ; also on sheet 40
SGMII3_TXP_AMC_NET: AMC1.20(Tx1+) C376.2
SMB_SCL_IPMBL: AMC1.56(SCL_L) ; also on sheet 5
SMB_SDA_IPMBL: AMC1.71(SDA_L) ; also on sheet 5
SOC_DDR3A_A0: U31.N3(A0) U39.N3(A0) ; also on sheet 1 20
SOC_DDR3A_A1: U31.P7(A1) U39.P7(A1) ; also on sheet 1 20
SOC_DDR3A_A2: U31.P3(A2) U39.P3(A2) ; also on sheet 1 20
SOC_DDR3A_A3: U31.N2(A3) U39.N2(A3) ; also on sheet 1 20
SOC_DDR3A_A4: U31.P8(A4) U39.P8(A4) ; also on sheet 1 20
SOC_DDR3A_A5: U31.P2(A5) U39.P2(A5) ; also on sheet 1 20
SOC_DDR3A_A6: U31.R8(A6) U39.R8(A6) ; also on sheet 1 20
SOC_DDR3A_A7: U31.R2(A7) U39.R2(A7) ; also on sheet 1 20
SOC_DDR3A_A8: U31.T8(A8) U39.T8(A8) ; also on sheet 1 20
SOC_DDR3A_A9: U31.R3(A9) U39.R3(A9) ; also on sheet 1 20
SOC_DDR3A_A10: U31.L7(A10/AP) U39.L7(A10/AP) ; also on sheet 1 20
SOC_DDR3A_A11: U31.R7(A11) U39.R7(A11) ; also on sheet 1 20
SOC_DDR3A_A12: U31.N7(A12/BC#) U39.N7(A12/BC#) ; also on sheet 1 20
SOC_DDR3A_A13: U31.T3(A13) U39.T3(A13) ; also on sheet 1 20
SOC_DDR3A_A14: U31.T7(A14) U39.T7(A14) ; also on sheet 1 20
SOC_DDR3A_A15: U31.M7(NC.3) U39.M7(NC.3) ; also on sheet 1 20
SOC_DDR3A_BA_0: U31.M2(BA0) U39.M2(BA0) ; also on sheet 1 20
SOC_DDR3A_BA_1: U31.N8(BA1) U39.N8(BA1) ; also on sheet 1 20
SOC_DDR3A_BA_2: U31.M3(BA2) U39.M3(BA2) ; also on sheet 1 20
SOC_DDR3A_CAS#: U31.K3(CAS#) U39.K3(CAS#) ; also on sheet 1 20
SOC_DDR3A_CKE_0: U31.K9(CKE) U39.K9(CKE) ; also on sheet 1 20
SOC_DDR3A_CKE_1: U31.J9(NC.4) U39.J9(NC.4) ; also on sheet 1 20
SOC_DDR3A_CKN_0: U31.K7(CK#) U39.K7(CK#) ; also on sheet 1 20
SOC_DDR3A_CKP_0: U31.J7(CK) U39.J7(CK) ; also on sheet 1 20
SOC_DDR3A_CS_0#: U31.L2(CS#) U39.L2(CS#) ; also on sheet 1 20
SOC_DDR3A_CS_1#: U31.L1(NC.2) U39.L1(NC.2) ; also on sheet 1 20
SOC_DDR3A_DM_6: U39.E7(LDM) ; also on sheet 1
SOC_DDR3A_DM_7: U39.D3(UDM) ; also on sheet 1
SOC_DDR3A_DM_8: U31.E7(LDM) ; also on sheet 1
SOC_DDR3A_DQ48: U39.F2(DQ2) ; also on sheet 1
SOC_DDR3A_DQ49: U39.F8(DQ3) ; also on sheet 1
SOC_DDR3A_DQ50: U39.F7(DQ1) ; also on sheet 1
SOC_DDR3A_DQ51: U39.E3(DQ0) ; also on sheet 1
SOC_DDR3A_DQ52: U39.H3(DQ4) ; also on sheet 1
SOC_DDR3A_DQ53: U39.H8(DQ5) ; also on sheet 1
SOC_DDR3A_DQ54: U39.G2(DQ6) ; also on sheet 1
SOC_DDR3A_DQ55: U39.H7(DQ7) ; also on sheet 1
SOC_DDR3A_DQ56: U39.A3(DQ15) ; also on sheet 1
SOC_DDR3A_DQ57: U39.C3(DQ9) ; also on sheet 1
SOC_DDR3A_DQ58: U39.A2(DQ13) ; also on sheet 1
SOC_DDR3A_DQ59: U39.C2(DQ11) ; also on sheet 1
SOC_DDR3A_DQ60: U39.D7(DQ8) ; also on sheet 1
SOC_DDR3A_DQ61: U39.A7(DQ12) ; also on sheet 1
SOC_DDR3A_DQ62: U39.B8(DQ14) ; also on sheet 1
SOC_DDR3A_DQ63: U39.C8(DQ10) ; also on sheet 1
SOC_DDR3A_DQSN_6: U39.G3(LDQS#) ; also on sheet 1
SOC_DDR3A_DQSN_7: U39.B7(UDQS#) ; also on sheet 1
SOC_DDR3A_DQSN_8: U31.G3(LDQS#) ; also on sheet 1
SOC_DDR3A_DQSP_6: U39.F3(LDQS) ; also on sheet 1
SOC_DDR3A_DQSP_7: U39.C7(UDQS) ; also on sheet 1
SOC_DDR3A_DQSP_8: U31.F3(LDQS) ; also on sheet 1
SOC_DDR3A_ECC0: U31.H8(DQ5) ; also on sheet 1
SOC_DDR3A_ECC1: U31.H7(DQ7) ; also on sheet 1
SOC_DDR3A_ECC2: U31.F2(DQ2) ; also on sheet 1
SOC_DDR3A_ECC3: U31.E3(DQ0) ; also on sheet 1
SOC_DDR3A_ECC4: U31.G2(DQ6) ; also on sheet 1
SOC_DDR3A_ECC5: U31.F8(DQ3) ; also on sheet 1
SOC_DDR3A_ECC6: U31.F7(DQ1) ; also on sheet 1
SOC_DDR3A_ECC7: U31.H3(DQ4) ; also on sheet 1
SOC_DDR3A_ODT_0: U31.K1(ODT) U39.K1(ODT) ; also on sheet 1 20
SOC_DDR3A_ODT_1: U31.J1(NC.1) U39.J1(NC.1) ; also on sheet 1 20
SOC_DDR3A_RAS#: U31.J3(RAS#) U39.J3(RAS#) ; also on sheet 1 20
SOC_DDR3A_RESETN: U31.T2(RESET#) U39.T2(RESET#) ; also on sheet 1 20
SOC_DDR3A_WE#: U31.L3(WE#) U39.L3(WE#) ; also on sheet 1 20
SOC_I2C1_SCL: U40.6(SCL) ; also on sheet 28 29
SOC_I2C1_SDA: U40.5(SDA) ; also on sheet 28 29
SOC_MDC_2V5: AMC1.129(Rx15-) R866.1 ; also on sheet 2 12
SOC_MDIO_2V5: AMC1.130(Rx15+) ; also on sheet 2 12
TCLKC_N: AMC1.135(TCLKC-) R789.2
TCLKC_P: AMC1.136(TCLKC+) R793.1
TIMO0_EVM_FPGA_1V8: R789.1 ; also on sheet 26 28
VTT_DDR3A: C161.2 C163.2 C172.2 CT8.1 TP54.1 U24.3(VO) U24.5(VOSNS) ; also on sheet 1 37
N17697231: R705.2 U39.L8(ZQ)
N17699058: R647.1 U31.C7(UDQS)
N17699064: R646.1 U31.B7(UDQS#)
N17699189: R649.1 U31.D3(UDM)
N17699210: R648.2 U31.L8(ZQ)
N17699240: R657.2 U31.C3(DQ9)
N17699246: R628.2 U31.C8(DQ10)
N17699252: R644.2 U31.A7(DQ12)
N17699256: R652.2 U31.A2(DQ13)
N17699260: R658.2 U31.C2(DQ11)
N17699270: R650.2 U31.A3(DQ15)
N17699272: R629.2 U31.B8(DQ14)
N17725715: R413.1 R734.2 U40.3(E2)
N17726358: R402.1 R723.2 U40.2(E1)
N17726610: R395.1 R717.2 U40.1(E0)
N17727285: R724.1 U40.7(~{WC})
N19393844: C140.1 R194.1 R206.2 U24.1(REFIN)
N19907643: R627.2 U31.L9(NC.5)
N19908216: R685.2 U39.L9(NC.5)
N22917936: C981.1 R866.2

Not connected (* = marked no-connect by the designer): AMC1 6(RSRVD6)* 8(RSRVD8)* 29(Tx2+)* 30(Tx2-)* 32(Rx2+)* 33(Rx2-)* 35(Tx3+)* 36(Tx3-)* 38(Rx3+)* 39(Rx3-)* 50(Tx5+)* 51(Tx5-)* 53(Rx5+)* 54(Rx5-)* 65(Tx7+)* 66(Tx7-)* 68(Rx7+)* 69(Rx7-)* 74(TCLKA+)* 75(TCLKA-)* 87(Rx8-)* 88(Rx8+)* 90(Tx8-)* 91(Tx8+)* 93(Rx9-)* 94(Rx9+)* 96(Tx9-)* 97(Tx9+)* 99(Rx10-)* 100(Rx10+)* 102(Tx10-)* 103(Tx10+)* 105(Rx11-)* 106(Rx11+)* 108(Tx11-)* 109(Tx11+)* 111(Rx12-)* 112(Rx12+)* 114(Tx12-)* 115(Tx12+)* 117(Rx13-)* 118(Rx13+)* 120(Tx13-)* 121(Tx13+)* 123(Rx14-)* 124(Rx14+)* 126(Tx14-)* 127(Tx14+)* 132(Tx15-)* 133(Tx15+)*

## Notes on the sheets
sheet 18
- AMC connector
- JTAG
- Management Power
- external RP1CLK
- Expansion I2C
- AIF CLK & FS
- SGMII[1:0]
- AIF[1:0]
- TCLKD also serves as a 30.72MHz LVDS clock to CLK1
  PRI_REF for the AIF synchronization
- TCLKCp/n alsp servers as the DSP_TIMI0
  and DSP_TIMO0 and 3.3V I/O respectively
- TCLKC_P : output for DSP_TIMI0
- TCLKC_N : intput for DSP_TIMO0
- PCIe[0]
- LAYOUT NOTE:
  Place these components
  close to  AMC EDGE
  connector
- PCIe[1]
- TCLKB also serves as a 25.0MHz LVDS clock to
  CLK3 PRI_REF for the HyperLink synchronization.
sheet 19
- DDR3(2), 3.3vaux -> .75v DDR3 Vt, DDR3 SPD EEPROM
- FOR ECC USE
- Trace need 20 mil.
- Trace needs 20 mil.
- * DDR3 pin M7 is used for
  A15 as per JEDC standard
- * DDR3 pin M7 is used for
  A15 as per JEDC standard
- DDR3-XXXX
  DiscreteSDRAM Array
- SPD EEPROM
- VCC0V75
- Address: 0x53
- 0.75V @1A
